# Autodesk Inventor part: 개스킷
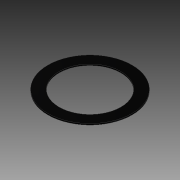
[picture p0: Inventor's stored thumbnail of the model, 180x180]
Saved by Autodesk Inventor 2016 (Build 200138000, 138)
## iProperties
Created: 2022-05
Part Number: 개스킷
Material: 황동, 연질 노란색
Document SubType Name: Modeling
Designer: mdu-01
Density: 1 g/cm^3
Appearance: 매끄러움 - 검은색
Author: mdu-01
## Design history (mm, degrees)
sketch "스케치1"
  geometry: C1 r 23.5 at (0, 0); C2 r 32 at (0, 0); 1 further point
  constraints: 2 centre point, 2 coincident
  dimensions: "d0" = 47 diameter of C1; "d1" = 64 diameter of C2
extrude "돌출1" new body sketch "스케치1" stored distance "d2" = 1; taper "d3" = 0 deg
node "솔리드1"
